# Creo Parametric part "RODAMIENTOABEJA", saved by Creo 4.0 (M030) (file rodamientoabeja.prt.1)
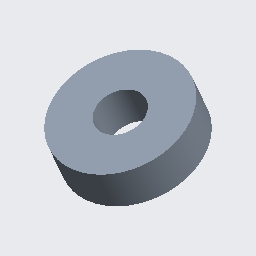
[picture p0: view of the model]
Units: millimeter Newton Second (mmNs); MM, TONNE, SECS

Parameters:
  MODELED_BY = "aj"

Created from: MMNS_PART_SOLID.PRT

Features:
  1. datum plane "RIGHT"
  2. datum plane "TOP"
  3. datum plane "FRONT"
  4. coordinate system
  5. extrusion "Extrude 1"

Surfaces: 2 plane, 2 cylinder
